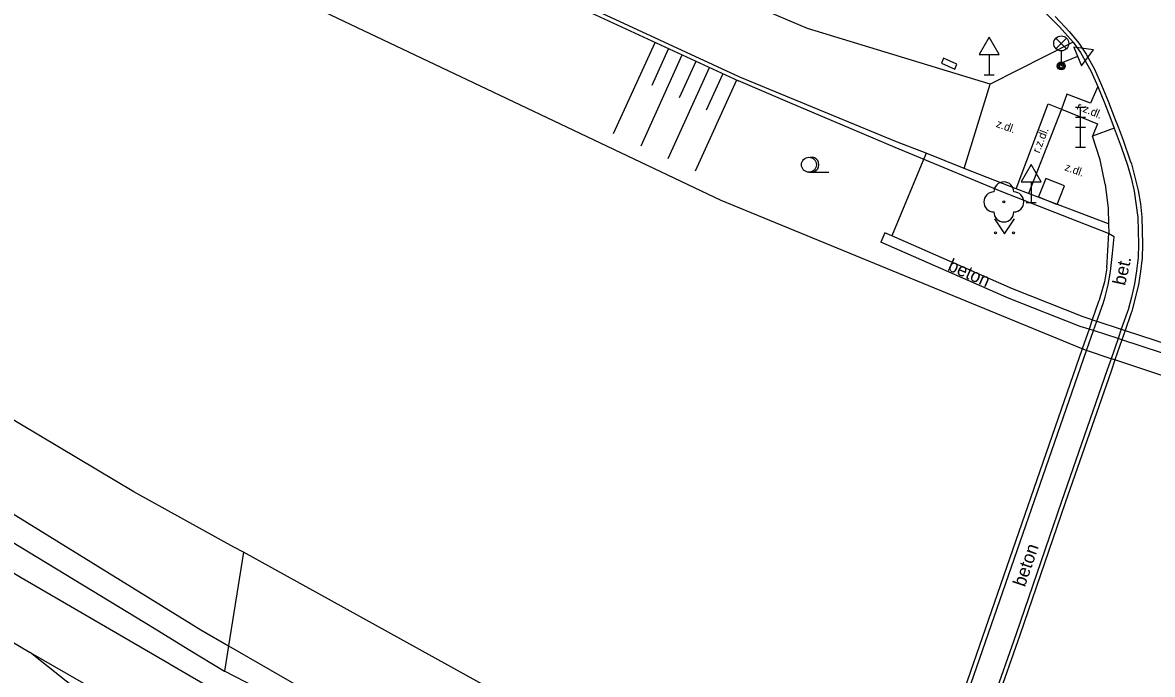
# Model space of a CAD drawing. Extents: x -598932 to -598196, y -1162207 to -1161504.
# Drawn here: x -598623.8 to -598567.3, y -1162031.8 to -1161999.2 of the extents above; entities that cross this region are included whole.
import ezdxf

# ---------------------------------------------------------------- set-up
doc = ezdxf.new("R2010")
doc.units = 0
for name, color, linetype in [('Level 22', 7, 'Continuous'), ('Level 26', 7, 'Continuous'), ('Level 33', 7, 'Continuous'), ('Level 34', 7, 'Continuous'), ('Level 36', 7, 'Continuous'), ('silnoproud - povrch.  znaky a  RIS  skut. velikost', 7, 'Continuous'), ('specificka linie pasportu komunikaci', 7, 'Continuous'), ('TM - chodniky - VP', 7, 'Continuous'), ('TM - hladina vodniho toku_ bazenu_ nadrze', 7, 'Continuous'), ('TM - hladina vodniho toku_ bazenu_ nadrze - shora neviditelny prubeh', 7, 'Continuous'), ('TM - horni hrana svahu', 7, 'Continuous'), ('TM - hranice souvisleho porostu (skupiny stromu_ kere)', 7, 'Continuous'), ('TM - komunikace - VP', 7, 'Continuous'), ('TM - pomocna konstrukcna linie', 7, 'Continuous'), ('TM - popis povrchu', 7, 'Continuous'), ('TM - rozhrani mezi zpev. plochami mezi sebou - VP', 7, 'Continuous'), ('TM - rozhrani ploch obecne - NP', 7, 'Continuous'), ('TM - rozhrani ploch obecne - VP', 7, 'Continuous'), ('TM - srafovani', 7, 'Continuous'), ('TM - zabradli - VP', 7, 'Continuous')]:
    doc.layers.add(name, color=color, linetype=linetype)

msp = doc.modelspace()

# ---------------------------------------------------------------- linework, layer by layer
at = {"layer": 'Level 22'}
msp.add_circle((-598574.75, -1162008.18), 0.05, dxfattribs=at)
for centre, start, end in [((-598574.75, -1162007.68), 0, 180), ((-598575.25, -1162008.18), 90, 270), ((-598574.25, -1162008.18), 270, 90), ((-598574.75, -1162008.68), 180, 0)]:
    msp.add_arc(centre, 0.5, start, end, dxfattribs=at)
at = {"layer": 'Level 26'}
msp.add_lwpolyline([(-598573.02, -1162007.929), (-598572.091, -1162008.3), (-598571.72, -1162007.371), (-598572.649, -1162007)], close=True, dxfattribs=at)
at = {"layer": 'Level 33'}
for p, q in [((-598572.145, -1162000.52), (-598571.615, -1161999.99)), ((-598572.145, -1161999.99), (-598571.615, -1162000.52)), ((-598571.88, -1162000.63), (-598571.88, -1162001.38)), ((-598571.17, -1162003.44), (-598570.67, -1162003.44)), ((-598570.92, -1162005.44), (-598570.92, -1162003.44)), ((-598571.17, -1162003.94), (-598570.67, -1162003.94)), ((-598571.17, -1162004.44), (-598570.67, -1162004.44)), ((-598571.17, -1162005.44), (-598570.67, -1162005.44))]:
    msp.add_line(p, q, dxfattribs=at)
for centre, radius in [((-598571.88, -1162000.255), 0.375), ((-598571.88, -1162001.38), 0.2), ((-598571.88, -1162001.38), 0.145), ((-598571.88, -1162001.38), 0.0876)]:
    msp.add_circle(centre, radius, dxfattribs=at)
at = {"layer": 'Level 34'}
for p, q in [((-598575.49, -1162000.812), (-598575.49, -1162001.83)), ((-598571.061, -1162000.908), (-598572, -1162001.3)), ((-598575.74, -1162001.83), (-598575.24, -1162001.83)), ((-598573.39, -1162007.182), (-598573.39, -1162008.2)), ((-598573.64, -1162008.2), (-598573.14, -1162008.2))]:
    msp.add_line(p, q, dxfattribs=at)
for points in [[(-598575.99, -1162000.812), (-598574.99, -1162000.812), (-598575.49, -1161999.946)], [(-598571.253, -1162000.446), (-598570.868, -1162001.369), (-598570.262, -1162000.574)], [(-598573.89, -1162007.182), (-598572.89, -1162007.182), (-598573.39, -1162006.316)]]:
    msp.add_lwpolyline(points, close=True, dxfattribs=at)
at = {"layer": 'Level 36'}
msp.add_line((-598584.49, -1162006.695), (-598583.49, -1162006.695), dxfattribs=at)
msp.add_lwpolyline([(-598575.21, -1162009.02), (-598574.71, -1162009.77), (-598574.21, -1162009.02)], dxfattribs=at)
for centre, radius in [((-598584.49, -1162006.32), 0.375), ((-598575.16, -1162009.72), 0.05), ((-598574.261, -1162009.72), 0.05)]:
    msp.add_circle(centre, radius, dxfattribs=at)
msp.add_arc((-598584.365, -1162006.32), 0.375, 260.4059, 99.5941, dxfattribs=at)
at = {"layer": 'silnoproud - povrch.  znaky a  RIS  skut. velikost'}
for points in [[(-598577.76, -1162000.99), (-598577.87, -1162001.24)], [(-598577.87, -1162001.24), (-598577.2, -1162001.55)], [(-598577.09, -1162001.3), (-598577.76, -1162000.99)], [(-598577.2, -1162001.55), (-598577.09, -1162001.3)]]:
    msp.add_lwpolyline(points, dxfattribs=at)
at = {"layer": 'specificka linie pasportu komunikaci'}
for points in [[(-598660.86, -1162000.99), (-598659.11, -1162002.28), (-598657.898, -1162003.157), (-598642.5, -1162013.91), (-598640.82, -1162014.99), (-598629.64, -1162021.94), (-598627.93, -1162022.98), (-598617.22, -1162029.49), (-598615.52, -1162030.53), (-598613.699, -1162031.635)], [(-598612.76, -1162025.69), (-598613.499, -1162030.366), (-598613.699, -1162031.635)], [(-598613.699, -1162031.635), (-598613.693, -1162031.639), (-598605.587, -1162035.812), (-598597.2, -1162040.447)]]:
    msp.add_lwpolyline(points, dxfattribs=at)
at = {"layer": 'TM - chodniky - VP'}
for points in [[(-598584.57, -1161999.51), (-598587.08, -1161998.45), (-598592.84, -1161995.91), (-598597.08, -1161993.84), (-598601.24, -1161991.62), (-598607.52, -1161988.29), (-598613.13, -1161985.08), (-598616.99, -1161982.73), (-598621.32, -1161979.95), (-598625.58, -1161977.07), (-598629.77, -1161974.09), (-598633.88, -1161971), (-598640.88, -1161965.42), (-598652.64, -1161955.19)], [(-598704.49, -1161968.57), (-598691.55, -1161979.22), (-598684.46, -1161984.96), (-598668.2, -1161997.51), (-598651.17, -1162009.48), (-598647.71, -1162011.91), (-598638.16, -1162018.11), (-598637.86, -1162018.3), (-598633.86, -1162020.9), (-598623.87, -1162026.95), (-598616.47, -1162031.26)], [(-598587.95, -1162001.94), (-598595.94, -1161998.24), (-598603.81, -1161994.27), (-598611.54, -1161990.06)], [(-598575.44, -1162002.29), (-598584.57, -1161999.51)], [(-598571.29, -1162000.19), (-598575.44, -1162002.29)], [(-598585.37, -1162003.01), (-598585.65, -1162002.89), (-598587.95, -1162001.94)], [(-598580.11, -1162005.17), (-598585.37, -1162003.01)], [(-598569.52, -1162009.27), (-598573.52, -1162007.76), (-598574.14, -1162007.52), (-598574.82, -1162007.26), (-598576.74, -1162006.5), (-598578.63, -1162005.75), (-598580.11, -1162005.17)], [(-598569.52, -1162009.27), (-598569.5, -1162009.74)], [(-598569.6, -1162011.48), (-598569.5, -1162009.74)], [(-598569.6, -1162011.48), (-598569.72, -1162012.17), (-598569.99, -1162013.09)], [(-598569.99, -1162013.09), (-598570.01, -1162013.16)], [(-598570.01, -1162013.16), (-598570.33, -1162014.07)], [(-598630.16, -1162026.68), (-598625.4, -1162029.53), (-598623.42, -1162030.71)], [(-598623.42, -1162030.71), (-598612.67, -1162036.89), (-598610.02, -1162038.35), (-598601.64, -1162043.18)], [(-598616.47, -1162031.26), (-598616.42, -1162031.29), (-598600.21, -1162040.73)]]:
    msp.add_lwpolyline(points, dxfattribs=at)
at = {"layer": 'TM - hladina vodniho toku_ bazenu_ nadrze'}
for points in [[(-598600.59, -1162002.54), (-598610.64, -1161997.76), (-598630.3, -1161986.03), (-598655.22, -1161966.67), (-598668.85, -1161955.4), (-598703.18, -1161923.15)], [(-598613.24, -1162025.43), (-598618.24, -1162022.67), (-598632.33, -1162014.28), (-598643.84, -1162006.97), (-598654.48, -1161999.77), (-598668.82, -1161988.66), (-598680.42, -1161979.19), (-598691.8, -1161968.94), (-598710.7, -1161950.21), (-598717.792, -1161943.174), (-598718.3, -1161942.67)], [(-598570.83, -1162015.53), (-598588.88, -1162008.11), (-598600.59, -1162002.54)], [(-598579.96, -1162041.91), (-598591.05, -1162036.92), (-598599.56, -1162032.98), (-598612.76, -1162025.69), (-598613.24, -1162025.43)]]:
    msp.add_lwpolyline(points, dxfattribs=at)
at = {"layer": 'TM - hladina vodniho toku_ bazenu_ nadrze - shora neviditelny prubeh'}
for points in [[(-598570.61, -1162015.61), (-598570.83, -1162015.53)], [(-598569.39, -1162016.02), (-598570.61, -1162015.61)], [(-598569.2, -1162016.08), (-598569.39, -1162016.02)], [(-598561.23, -1162018.73), (-598569.2, -1162016.08)]]:
    msp.add_lwpolyline(points, dxfattribs=at)
at = {"layer": 'TM - horni hrana svahu'}
for points in [[(-598660.86, -1162000.99), (-598639.42, -1162014.42), (-598615.37, -1162029.27)], [(-598615.37, -1162029.27), (-598614.88, -1162029.57), (-598613.499, -1162030.366), (-598592.16, -1162042.67)], [(-598594.46, -1162051.52), (-598604.69, -1162045.61), (-598623.42, -1162030.71)]]:
    msp.add_lwpolyline(points, dxfattribs=at)
at = {"layer": 'TM - hranice souvisleho porostu (skupiny stromu_ kere)'}
msp.add_lwpolyline([(-598578.63, -1162005.75), (-598580.34, -1162009.88)], dxfattribs=at)
at = {"layer": 'TM - komunikace - VP'}
for points in [[(-598576.18, -1161996.61), (-598575.24, -1161997.01), (-598574.34, -1161997.5), (-598573.49, -1161998.07), (-598572.69, -1161998.71), (-598571.96, -1161999.42), (-598571.29, -1162000.19)], [(-598571.29, -1162000.19), (-598570.92, -1162000.71), (-598570.4, -1162001.63), (-598570.05, -1162002.41)], [(-598570.05, -1162002.41), (-598569.72, -1162003.23), (-598569.4, -1162004.05), (-598569.23, -1162004.49)], [(-598569.23, -1162004.49), (-598568.88, -1162005.43), (-598568.56, -1162006.34), (-598568.38, -1162006.98), (-598568.23, -1162007.64), (-598568.05, -1162008.96), (-598568.01, -1162010.29), (-598568.04, -1162010.96), (-598568.11, -1162011.62), (-598568.22, -1162012.28), (-598568.36, -1162012.94), (-598568.54, -1162013.58), (-598568.59, -1162013.71)], [(-598568.59, -1162013.71), (-598568.88, -1162014.54)], [(-598568.88, -1162014.54), (-598569.04, -1162015.01)], [(-598569.04, -1162015.01), (-598569.39, -1162016.02)], [(-598569.39, -1162016.02), (-598569.58, -1162016.57), (-598571.87, -1162023.15), (-598574.14, -1162029.77), (-598575.32, -1162033.13), (-598576.45, -1162036.39), (-598578.55, -1162042.46)]]:
    msp.add_lwpolyline(points, dxfattribs=at)
at = {"layer": 'TM - pomocna konstrukcna linie'}
msp.add_lwpolyline([(-598580.69, -1162009.73), (-598580.89, -1162010.19)], dxfattribs=at)
at = {"layer": 'TM - rozhrani mezi zpev. plochami mezi sebou - VP'}
for points in [[(-598576.74, -1162006.5), (-598575.44, -1162002.29)], [(-598570.05, -1162002.41), (-598570.42, -1162003.25), (-598571.6, -1162002.8), (-598571.87, -1162003.54)], [(-598574.14, -1162007.52), (-598572.53, -1162003.27), (-598571.87, -1162003.54)], [(-598571.87, -1162003.54), (-598573.52, -1162007.76)], [(-598571.87, -1162003.54), (-598570.06, -1162004.27), (-598570.31, -1162004.89)], [(-598569.23, -1162004.49), (-598570.31, -1162004.89)], [(-598569.93, -1162006.08), (-598570.31, -1162004.89)], [(-598569.69, -1162007.29), (-598569.93, -1162006.08)], [(-598569.69, -1162007.29), (-598569.54, -1162008.51), (-598569.52, -1162009.27)]]:
    msp.add_lwpolyline(points, dxfattribs=at)
at = {"layer": 'TM - rozhrani ploch obecne - NP'}
for points in [[(-598570.33, -1162014.07), (-598570.1, -1162014.14)], [(-598570.1, -1162014.14), (-598568.88, -1162014.54)], [(-598570.26, -1162014.61), (-598570.49, -1162014.54)], [(-598569.04, -1162015.01), (-598570.26, -1162014.61)], [(-598568.88, -1162014.54), (-598568.68, -1162014.6)], [(-598568.68, -1162014.6), (-598560.7, -1162017.21)], [(-598568.85, -1162015.07), (-598569.04, -1162015.01)], [(-598560.87, -1162017.69), (-598568.85, -1162015.07)]]:
    msp.add_lwpolyline(points, dxfattribs=at)
at = {"layer": 'TM - rozhrani ploch obecne - VP'}
for points in [[(-598572.18, -1161998.91), (-598571.46, -1161999.67), (-598571, -1162000.25), (-598570.64, -1162000.79), (-598570.22, -1162001.55), (-598569.86, -1162002.34), (-598569.53, -1162003.15), (-598569.21, -1162003.98), (-598569.04, -1162004.42), (-598568.79, -1162005.09), (-598568.43, -1162006.12), (-598568.37, -1162006.28), (-598568.04, -1162007.6), (-598567.92, -1162008.27), (-598567.85, -1162008.94), (-598567.81, -1162010.3), (-598567.84, -1162010.98), (-598567.91, -1162011.65), (-598568.02, -1162012.32), (-598568.35, -1162013.64), (-598568.4, -1162013.78)], [(-598570.78, -1162013.92), (-598574.31, -1162012.53), (-598580.34, -1162009.88), (-598580.69, -1162009.73)], [(-598570.93, -1162014.4), (-598574.49, -1162013), (-598580.89, -1162010.19)], [(-598570.33, -1162014.07), (-598570.78, -1162013.92)], [(-598570.33, -1162014.07), (-598570.49, -1162014.54)], [(-598568.4, -1162013.78), (-598568.68, -1162014.6)], [(-598570.49, -1162014.54), (-598570.93, -1162014.4)], [(-598570.49, -1162014.54), (-598570.83, -1162015.53)], [(-598568.68, -1162014.6), (-598568.85, -1162015.07)], [(-598568.85, -1162015.07), (-598569.2, -1162016.08)], [(-598570.83, -1162015.53), (-598576.73, -1162032.57)], [(-598569.2, -1162016.08), (-598569.39, -1162016.64), (-598571.68, -1162023.22), (-598573.95, -1162029.84), (-598575.13, -1162033.2), (-598576.26, -1162036.46), (-598578.37, -1162042.53)]]:
    msp.add_lwpolyline(points, dxfattribs=at)
at = {"layer": 'TM - srafovani'}
for points in [[(-598592.2, -1162000.23), (-598594.27, -1162004.78)], [(-598591.52, -1162000.54), (-598592.35, -1162002.36)], [(-598590.84, -1162000.85), (-598592.9, -1162005.4)], [(-598590.15, -1162001.16), (-598590.98, -1162002.98)], [(-598589.47, -1162001.47), (-598591.54, -1162006.02)], [(-598588.79, -1162001.78), (-598589.62, -1162003.6)], [(-598588.11, -1162002.09), (-598590.17, -1162006.64)]]:
    msp.add_lwpolyline(points, dxfattribs=at)
at = {"layer": 'TM - zabradli - VP'}
for points in [[(-598619.24, -1161985.76), (-598611.63, -1161990.23), (-598603.89, -1161994.45), (-598596.02, -1161998.42), (-598588.01, -1162002.13)], [(-598585.44, -1162003.22), (-598588.01, -1162002.12)], [(-598580.18, -1162005.46), (-598585.44, -1162003.22)], [(-598569.51, -1162009.76), (-598574.89, -1162007.66), (-598580.18, -1162005.46)], [(-598569.23, -1162009.93), (-598569.51, -1162009.76)], [(-598569.42, -1162011.65), (-598569.31, -1162010.75), (-598569.23, -1162009.93)], [(-598569.79, -1162013.25), (-598569.68, -1162012.93), (-598569.53, -1162012.32), (-598569.42, -1162011.65)], [(-598570.1, -1162014.14), (-598569.79, -1162013.25)], [(-598570.26, -1162014.61), (-598570.1, -1162014.14)], [(-598570.61, -1162015.61), (-598570.26, -1162014.61)], [(-598576.53, -1162032.67), (-598570.61, -1162015.61)]]:
    msp.add_lwpolyline(points, dxfattribs=at)

# ---------------------------------------------------------------- texts
at = {"layer": 'TM - popis povrchu'}
for s, height, rotation, p in [('r.z.dl.', 0.4, 338, (-598571.14, -1162003.54)), ('z.dl.', 0.4, 340, (-598575.17, -1162004.42)), ('r.z.dl.', 0.4, 69, (-598572.97, -1162005.77)), ('z.dl.', 0.4, 340, (-598571.74, -1162006.59)), ('beton', 0.65, 336.29, (-598577.6, -1162011.58)), ('bet.', 0.65, 77.27, (-598568.69, -1162012.39)), ('beton', 0.65, 71.07, (-598573.7, -1162027.46))]:
    msp.add_text(s, height=height, rotation=rotation, dxfattribs=at).set_placement(p)

doc.saveas('drawing.dxf')
